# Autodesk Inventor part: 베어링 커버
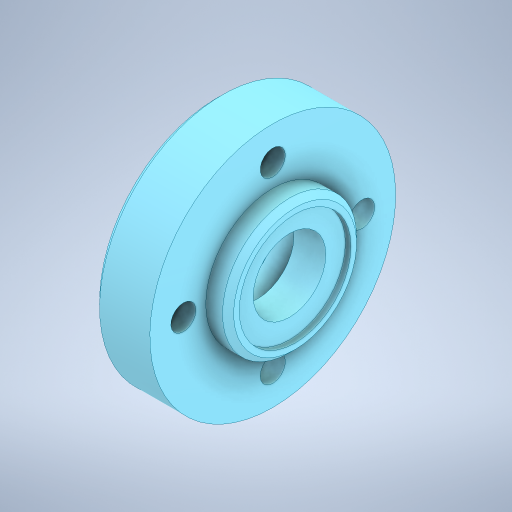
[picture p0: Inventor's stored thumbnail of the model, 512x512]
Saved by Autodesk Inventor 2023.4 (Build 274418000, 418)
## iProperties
Created: 2024-05
Part Number: 베어링 커버
Material: 강철, 연강
Document SubType Name: Modeling
Designer: user
Density: 7.85 g/cm^3
Appearance: 기본값
Author: jhkim
Sending System: Autodesk Inventor 2025
Preprocessor: ST-DEVELOPER v20
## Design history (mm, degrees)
feature "솔리드1"
node "솔리드2"
